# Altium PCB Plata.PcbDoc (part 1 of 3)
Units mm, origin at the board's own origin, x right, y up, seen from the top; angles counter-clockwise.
Board outline 225.2 x 126.25 mm, 5 copper layers (Top Layer, Mid-Layer 1, Mid-Layer 2, Mid-Layer 3, Bottom Layer); 204 components, 178 nets, 840 pads, 262 vias.
Unrouted connection lines stored in the file: 7.
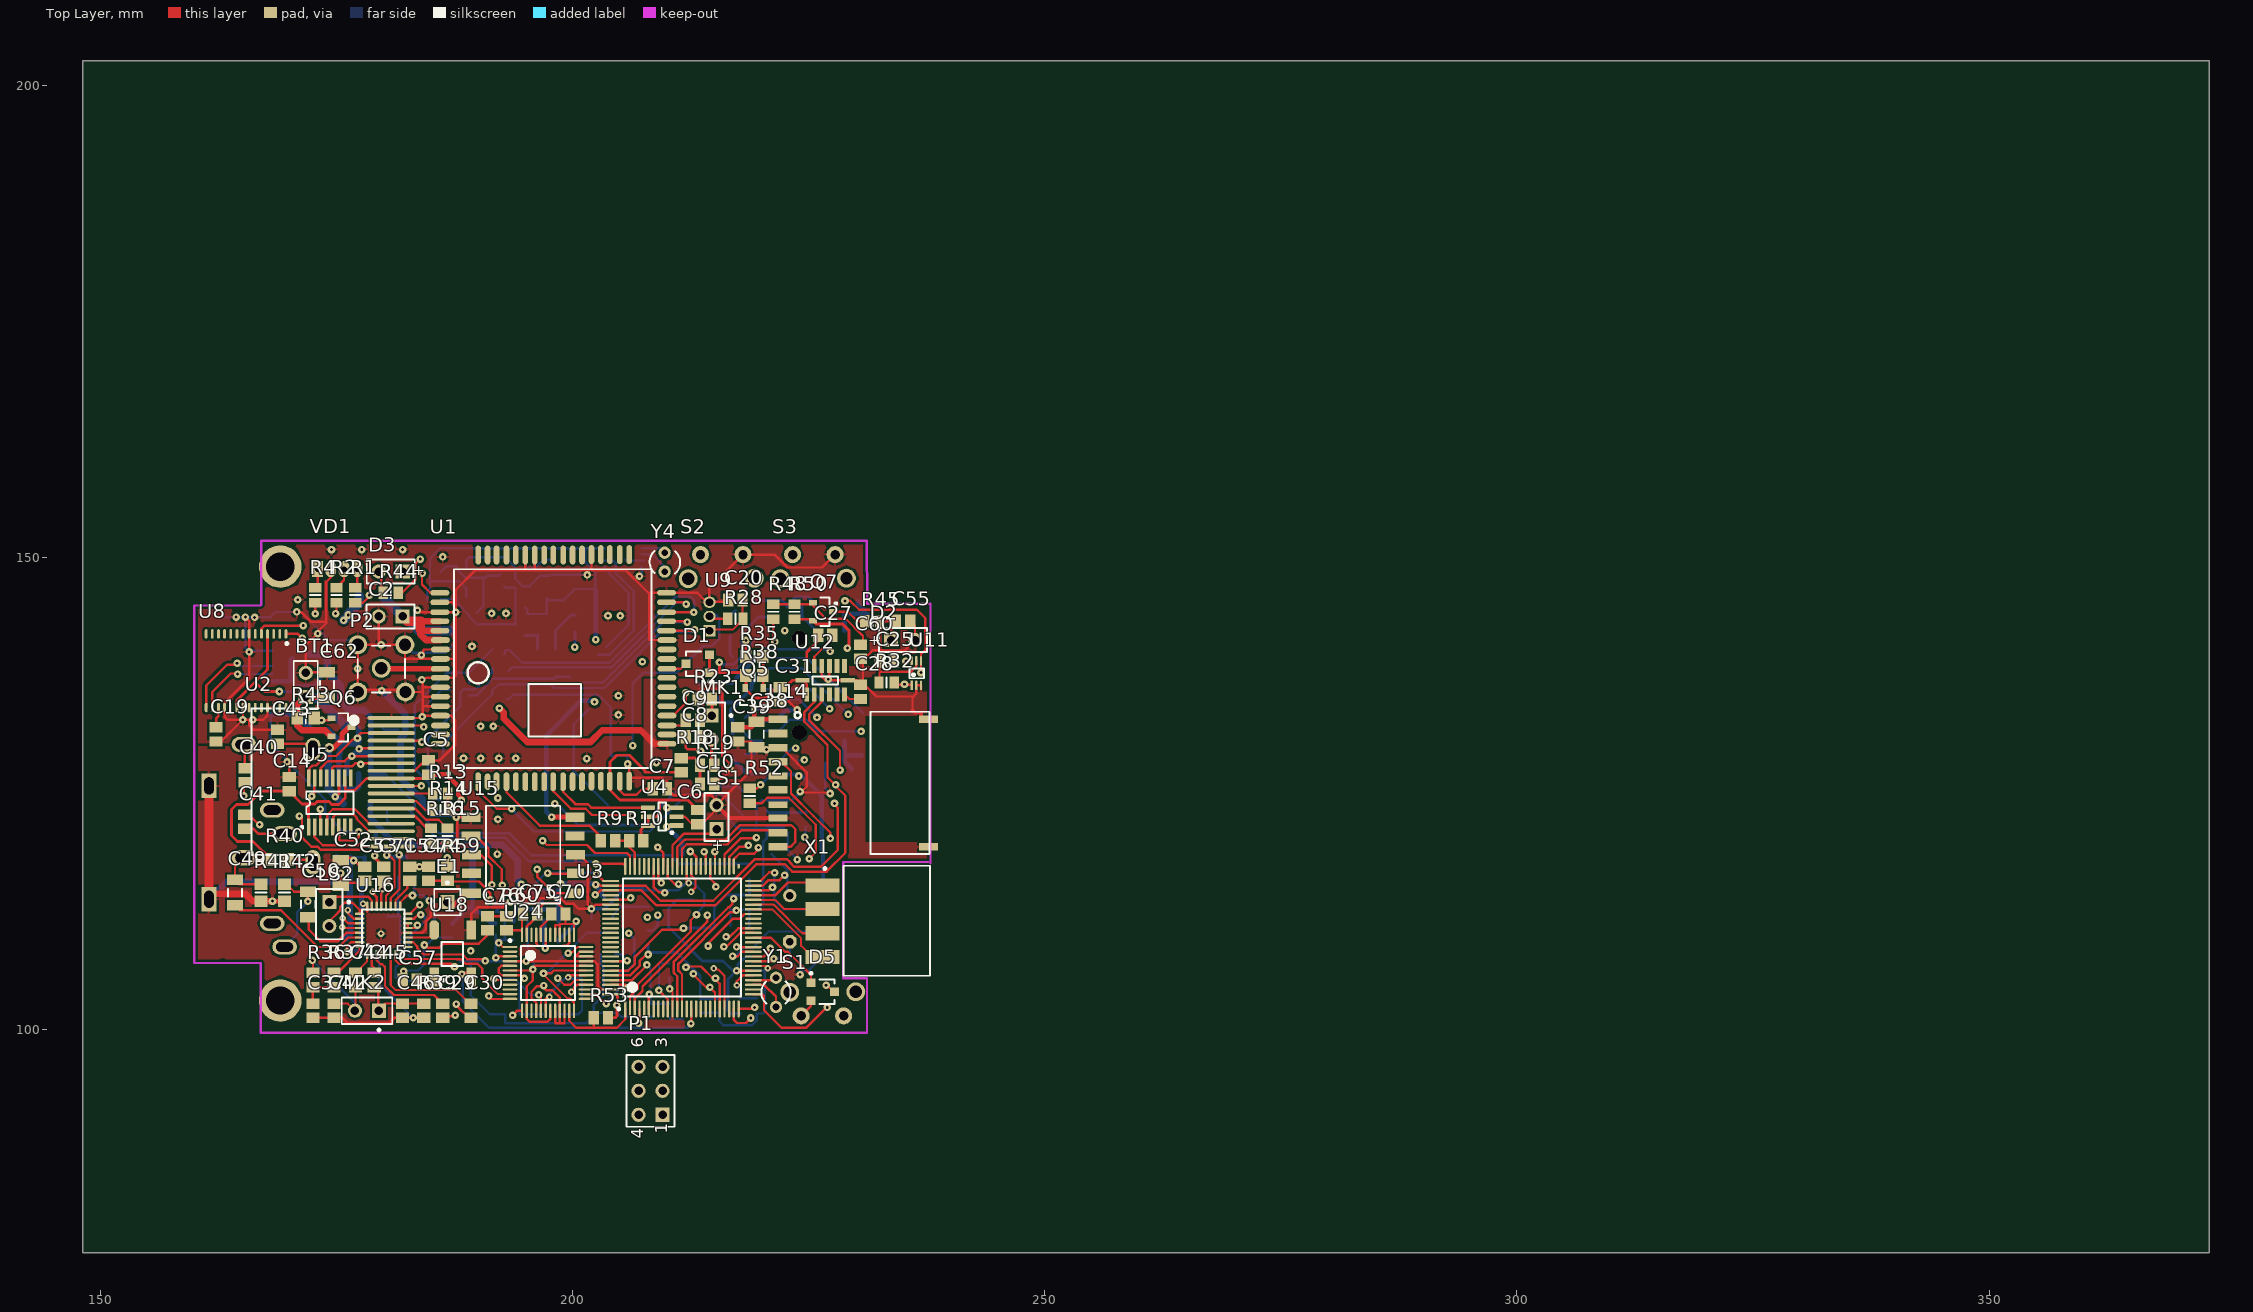
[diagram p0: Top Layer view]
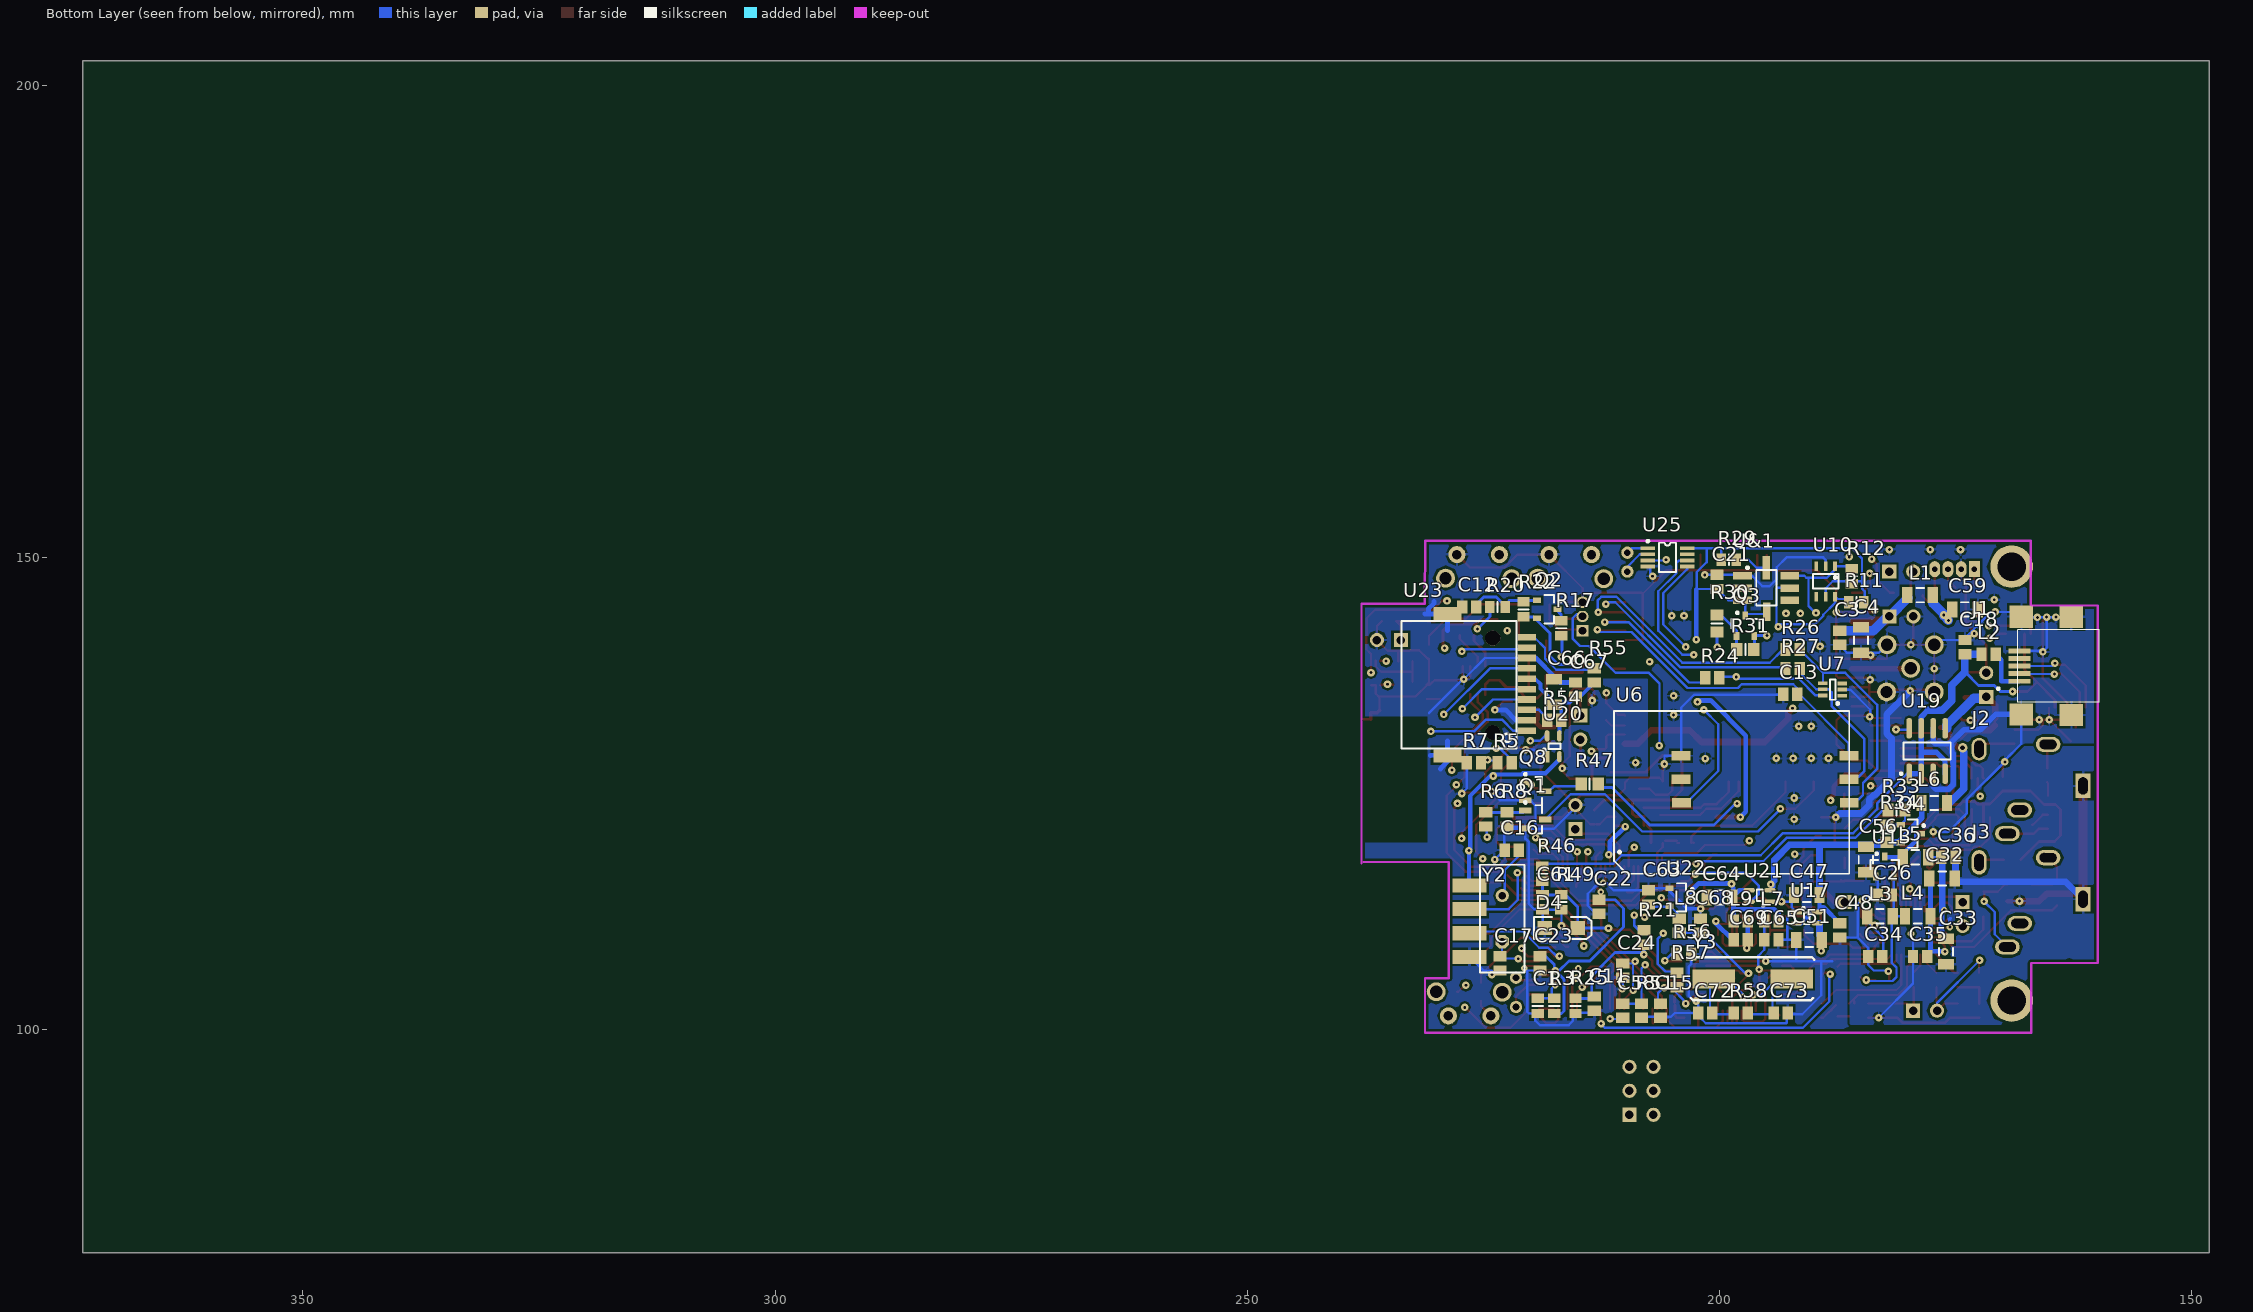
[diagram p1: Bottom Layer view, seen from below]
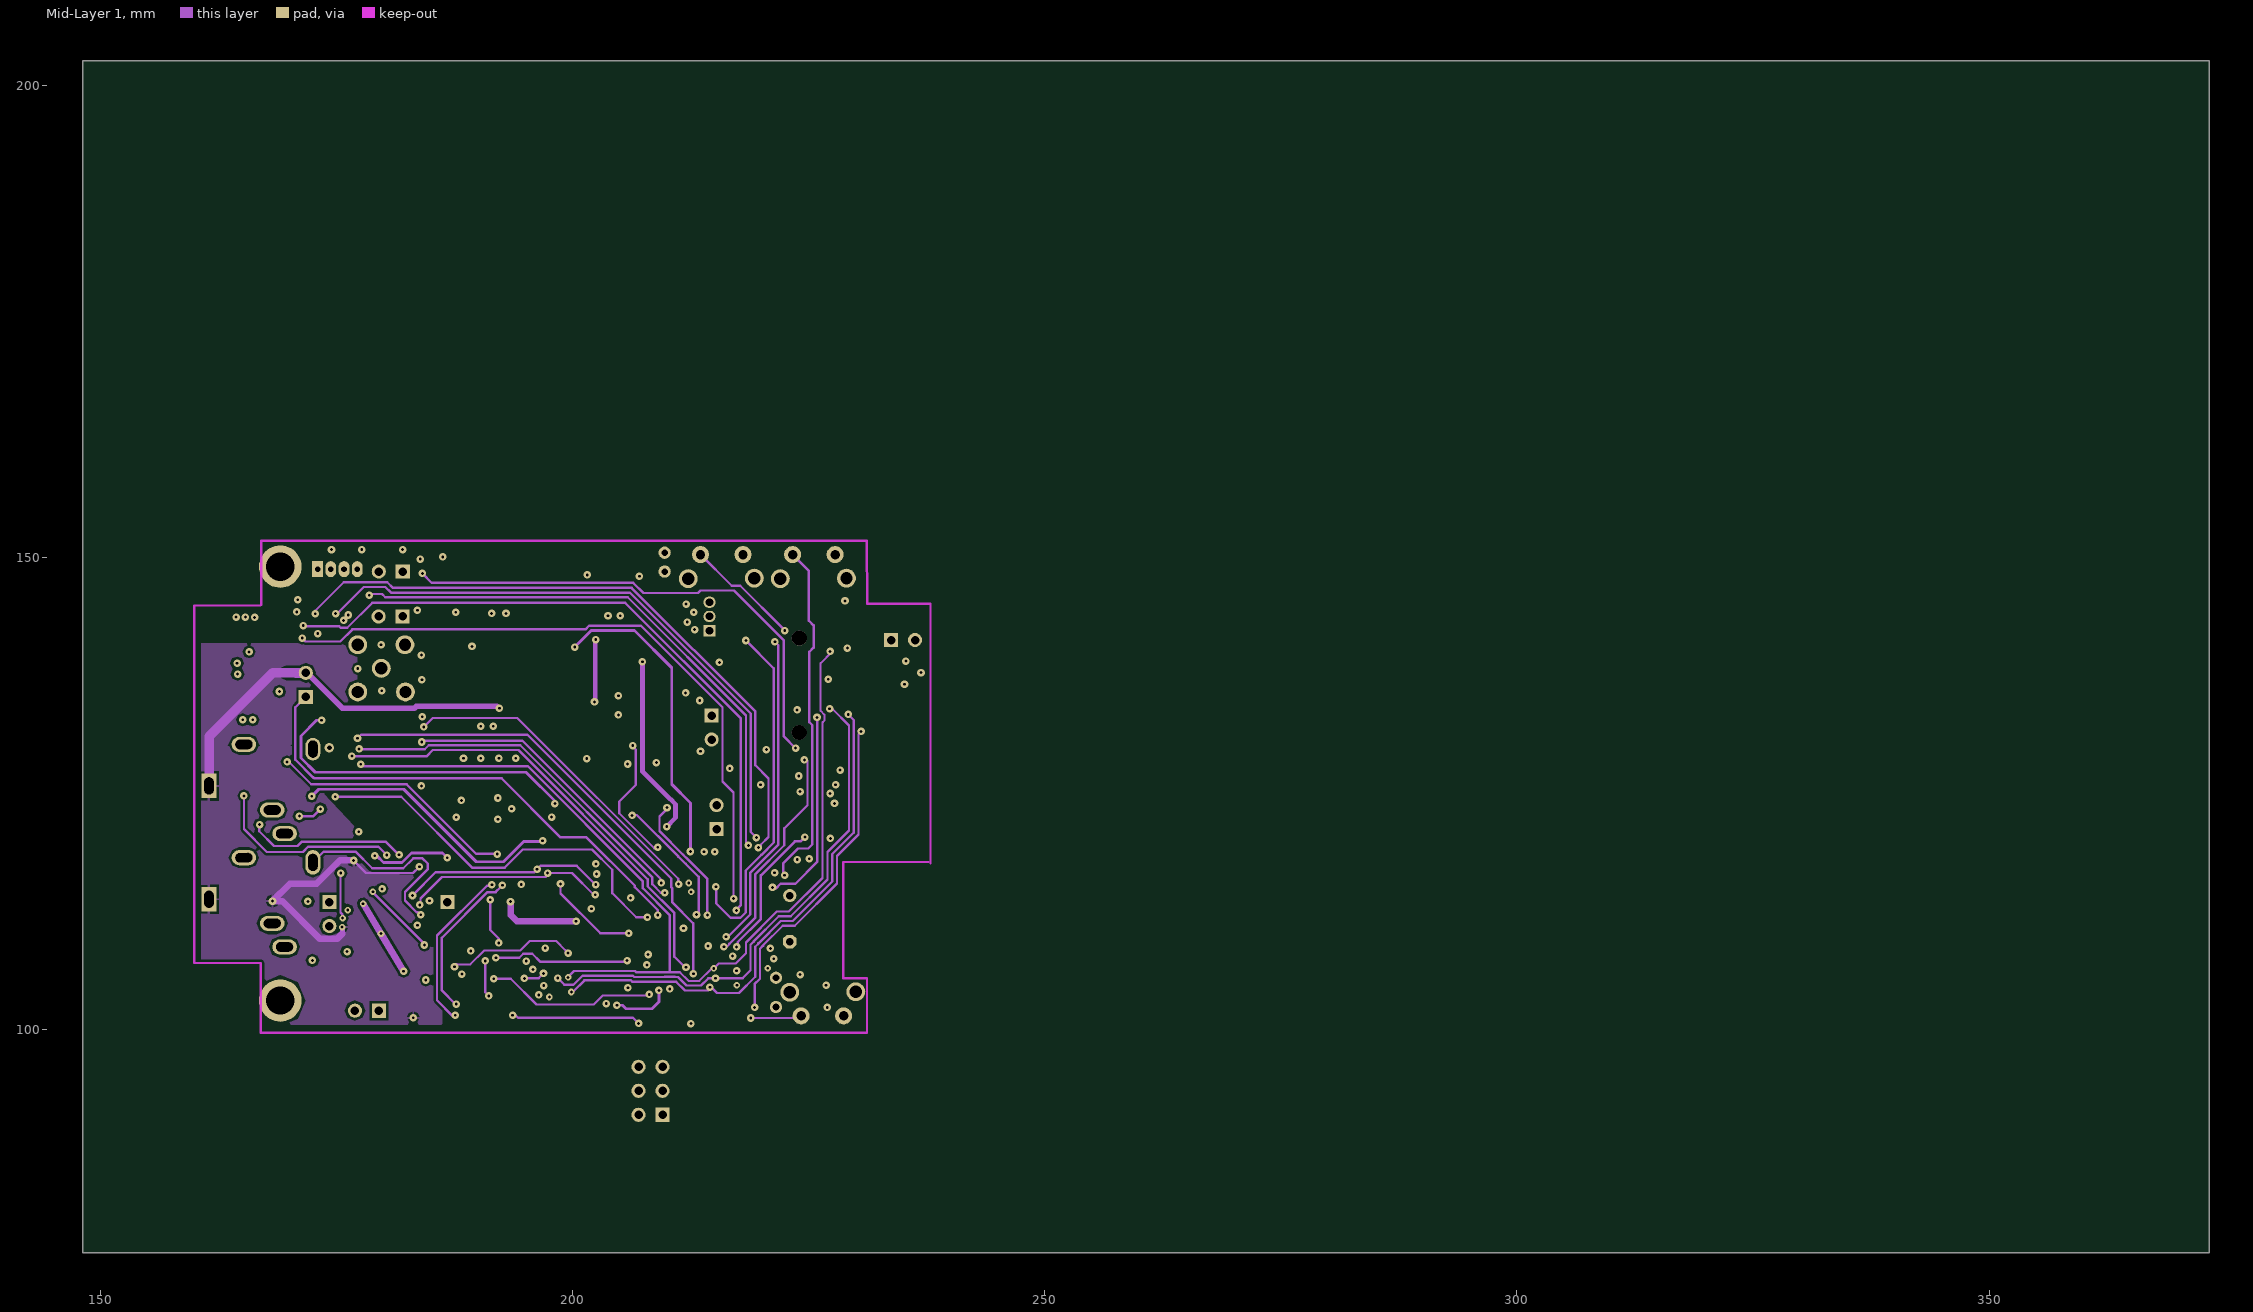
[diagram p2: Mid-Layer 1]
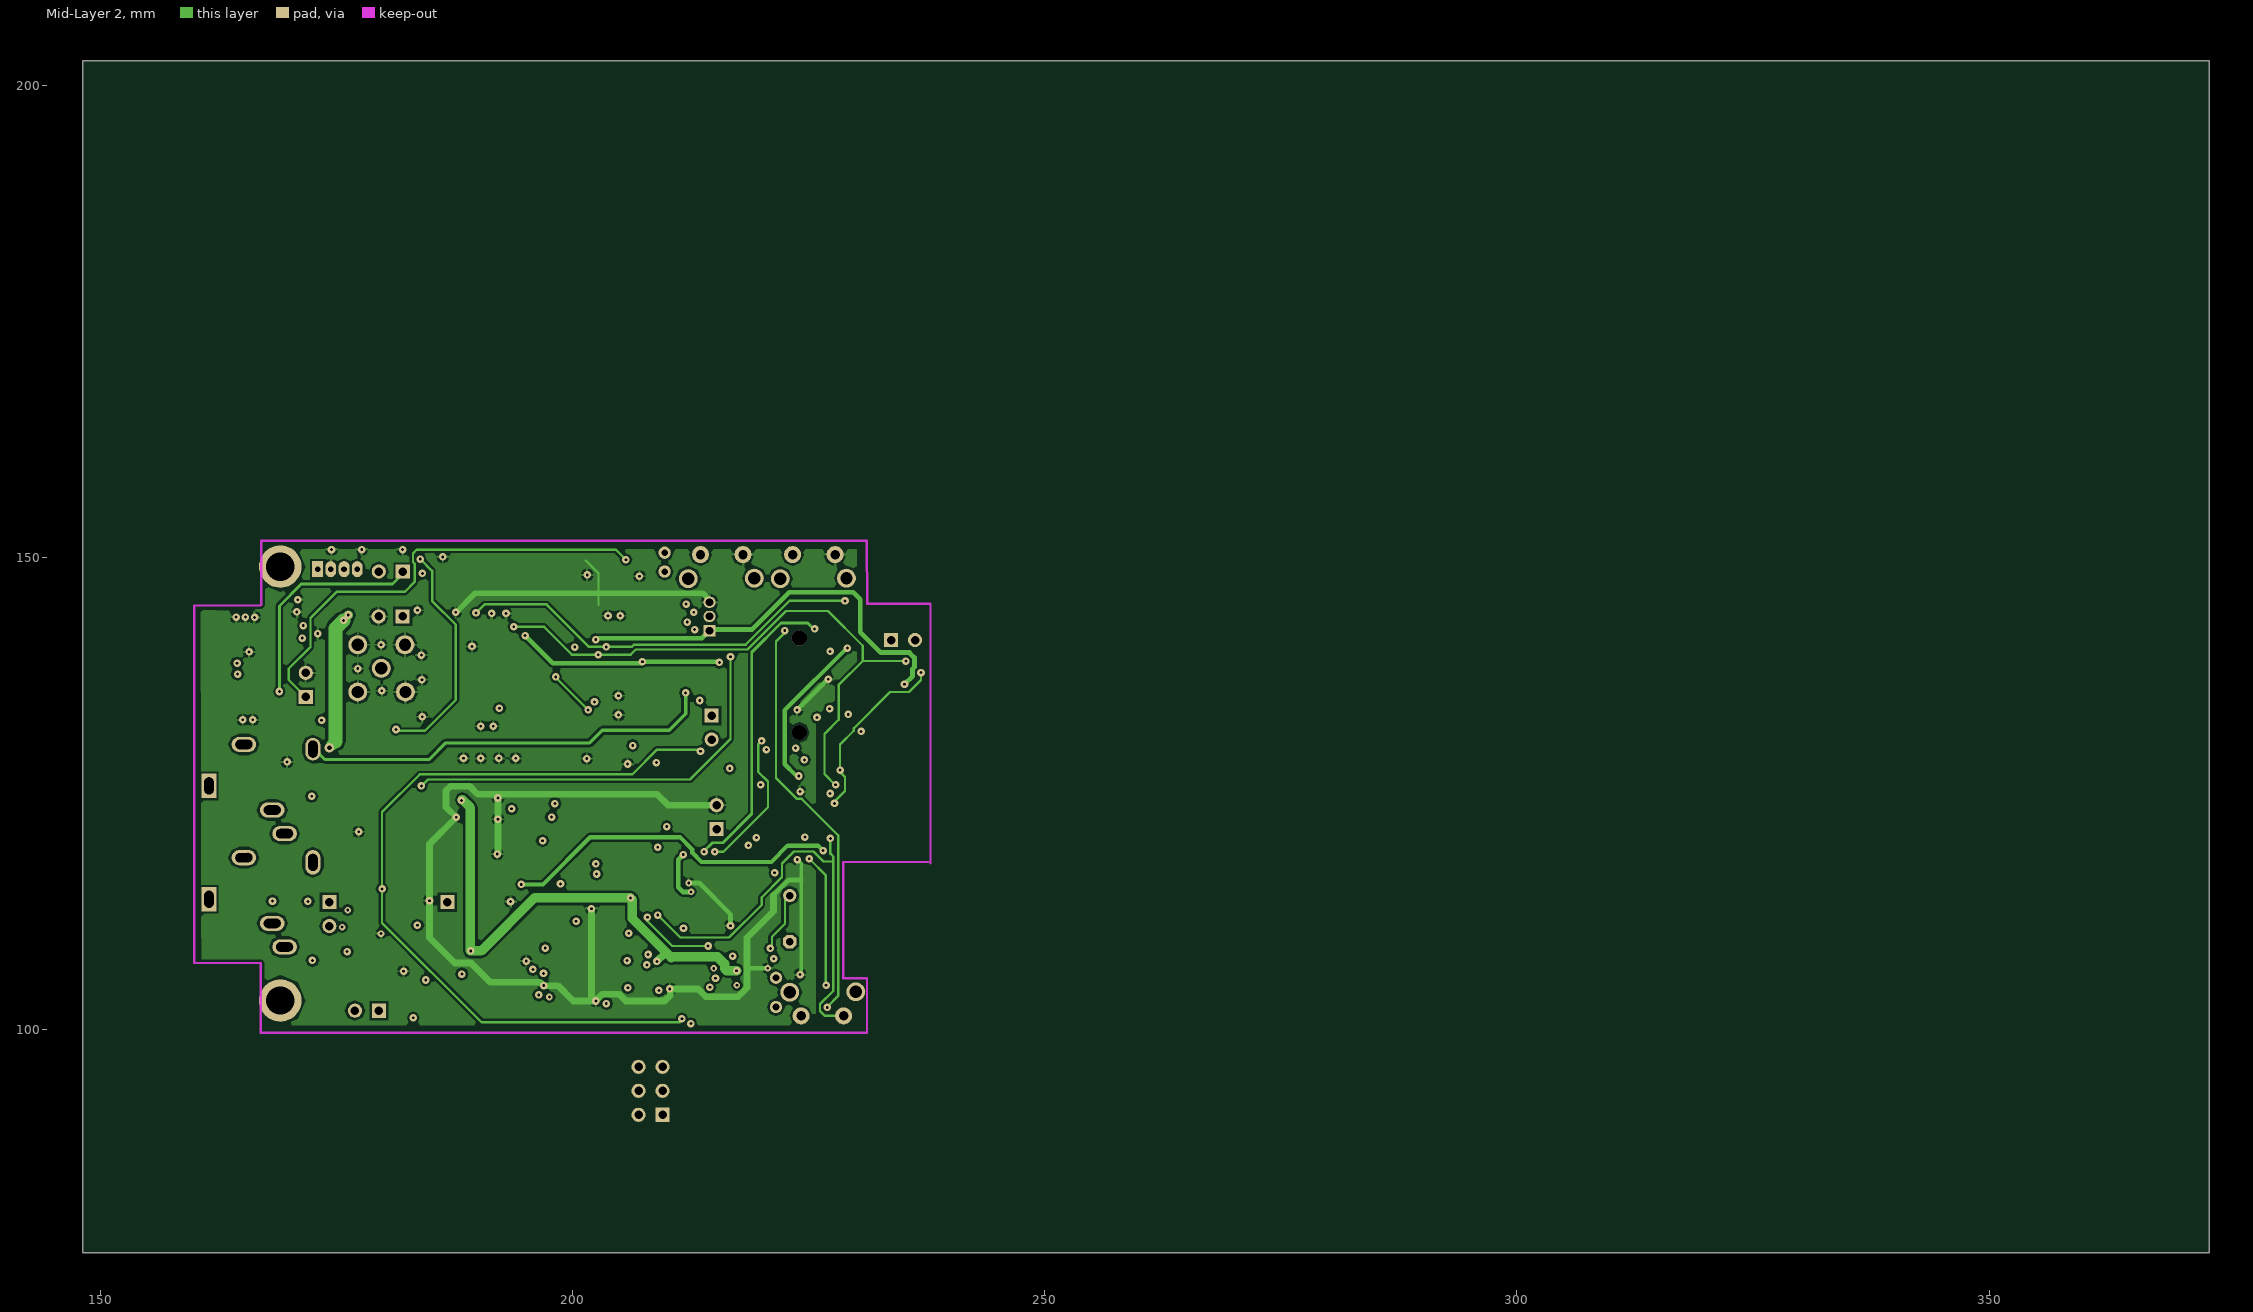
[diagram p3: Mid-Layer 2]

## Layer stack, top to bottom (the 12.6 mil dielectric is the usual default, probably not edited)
Top Layer: signal copper 0.0356
Dielectric: prepreg 0.32, FR-4, Dk 4.8
Mid-Layer 1: signal copper 0.0356
Dielectric: prepreg 0.32, FR-4, Dk 4.8
Mid-Layer 2: signal copper 0.0356
Dielectric: prepreg 0.32, FR-4, Dk 4.8
Mid-Layer 3: signal copper 0.0356
Dielectric: core 0.32, FR-4, Dk 4.8
Bottom Layer: signal copper 0.0356

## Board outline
148.125,202.6 373.325,202.6 373.325,76.35 148.125,76.35

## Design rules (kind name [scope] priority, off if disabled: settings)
AcuteAngle [All] p1: minimum=6.00000000000000E+0001
Clearance [All] p1: gap=0.25
Length Length_3 [All] p1: maxlimit=2540 minlimit=0
Length STEP4 [InNet('STEP4')] p2: maxlimit=254 minlimit=0
Length STEP3 [InNet('STEP3')] p3: maxlimit=254 minlimit=0
Length STEP2 [InNet('STEP2')] p4: maxlimit=254 minlimit=0
Length STEP1 [InNet('STEP1')] p5: maxlimit=254 minlimit=0
Length 1 [InNet('CLK')] p6: maxlimit=254 minlimit=0
MaximumViaCount [All] p1: limit=100
MinimumAnnularRing [All] p1: minimumring=0.25
PolygonConnect [All] p1: connectstyle=Relief reliefconductorwidth=0.254 reliefentries=4 polygonreliefangle="90 Angle"
RoomDefinition "Центральный процессор" [InComponentClass('Центральный процессор')] p1: confinementstyle=ConfineIn formatcopy=TRUE lockcomponents=FALSE outline 374.471,76.557 390.472,76.557 390.472,82.308 374.471,82.308
RoutingLayers [All] p1: top layer_v5=TRUE mid layer 1_v5=FALSE mid layer 2_v5=FALSE mid layer 3_v5=FALSE bottom layer_v5=TRUE
RoutingVias [All] p1: holewidth=0.3 width=0.8 viastyle="Through Hole" minholewidth=0.3 minwidth=0.8 maxholewidth=0.3 maxwidth=0.8
SMDToPlane [All] p1: distance=393701
SilkscreenOverComponentPads [All] p1: minsilkscreentomaskgap=0.254
SolderMaskExpansion [All] p1: expansion=0.102
Width VCC3 [InNet('VCC3')] p1: maxlimit=1 minlimit=0.25 preferedwidth=0.25
Width VCC5 [InNet('VCC5')] p2: maxlimit=1 minlimit=0.25 preferedwidth=0.25
Width GND [InNet('GND')] p3: maxlimit=1.4 minlimit=0.25 preferedwidth=0.25
Width [All] p4: maxlimit=0.55 minlimit=0.24 preferedwidth=0.25
26 further rules are at their usual default settings.

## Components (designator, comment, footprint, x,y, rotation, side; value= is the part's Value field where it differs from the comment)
BT1 "Battery" BAT-2 171.75,136.5 r90 top
C1 "Cap Semi" 6-0805_L 219.25,102.5 r90 bottom
C2 "Cap Pol2" HDR1X2 182,143.75 r180 top
C3 "Cap Semi" C0805 187.25,141.5 r270 bottom
C4 "Cap Semi" C1206 185,141.25 r270 bottom
C5 "Cap Semi" C0805 184.75,127.75 r90 top
C6 "Cap Semi" C0805 213.25,122.5 r90 top
C7 "Cap Semi" C0805 209.25,125.5 r180 top
C8 "Cap Semi" C0805 212.75,131 r180 top
C9 "Cap Semi" C0805 212.75,132.75 r180 top
C10 "Cap Semi" C0805 214.25,126 r180 top
C11 "Cap Semi" C0805 213.25,102.75 r90 bottom
C12 "Cap Semi" C0805 226.5,144.75 r0 bottom
C13 "Cap Semi" C0805 192.5,135.5 r180 bottom
C14 "Cap Semi" C0805 170,126 r90 top
C15 "Cap Semi" C0805 206.25,102 r90 bottom
C16 "Cap Semi" C0805 222,119 r0 bottom
C17 "Cap Semi" C0805 223.25,107 r270 bottom
C18 "Cap Semi" C0805 174,140.5 r270 bottom
C19 "Cap Semi" C0805 162.25,131.25 r90 top
C20 "Cap Semi" C0805 217.25,145.5 r180 top
C21 "Cap Semi" C0805 200.25,147.4 r270 bottom
C22 "Cap Semi" C0805 212.75,113 r90 bottom
C23 "Cap Semi" C0805 219,107 r90 bottom
C24 "Cap Semi" C0805 210.25,106.25 r90 bottom
C25 "Cap Semi" C0805 233.25,139 r0 top
C26 "Cap Semi" C0805 182.5,114.25 r180 bottom
C27 "Cap Semi" C0805 226.75,141.75 r0 top
C28 "Cap Semi" C0805 230.5,135.75 r270 top
C29 "Cap Semi" C0805 186.25,102 r90 top
C30 "Cap Semi" C0805 189.25,102 r90 top
C31 "Cap Semi" C0805 222,135.5 r270 top
C32 "Cap Pol2" C1206 176.425,116 r180 bottom
C33 "Cap Pol2" C1206 176,108.25 r270 bottom
C34 "Cap Semi" C0805 183.5,107.75 r0 bottom
C35 "Cap Semi" C0805 178.75,107.75 r0 bottom
C36 "Cap Semi" C0805 175.75,118.25 r180 bottom
C37 "Cap Semi" C0805 172.5,102 r270 top
C38 "Cap Pol2" C1206 219.5,131.25 r270 top
C39 "Cap Semi" C0805 217.5,131.25 r270 top
C40 "Cap Semi" C0805 165.299,126.937 r90 top
C41 "Cap Semi" C0805 165.25,122 r270 top
C42 "Cap Semi" C0805 174.75,102 r90 top
C43 "Cap Semi" C0805 168.75,131 r270 top
C44 "Cap Semi" C0805 177,105.25 r90 top
C45 "Cap Semi" C0805 179,105.25 r90 top
C46 "Cap Semi" C0805 182,102 r90 top
C47 "Cap Semi" C1206 190.75,114.25 r180 bottom
C48 "Cap Semi" C0805 187.25,110.5 r270 bottom
C49 "Cap Semi" C1206 164.25,114.5 r90 top
C50 "Cap Semi" C1206 172,113.25 r90 top
C51 "Cap Semi" C1206 190.5,109.5 r180 bottom
C52 "Cap Pol2" C1206 175.45,116.575 r90 top
C53 "Cap Semi" C0805 178,116.5 r90 top
C54 "Cap Semi" C0805 182.75,116.5 r90 top
C55 "Cap Semi" C0805 235,143.25 r180 top
C56 "Cap Semi" C1206 184.5,118 r270 bottom
C57 "Cap Semi" C0805 182.75,105.25 r180 top
C58 "Cap Semi" C0805 210.25,102 r90 bottom
C59 "Cap Semi" C1206 174,144.5 r180 bottom
C60 "Cap Semi" C0805 230.5,140 r90 top
C61 "Cap Semi" C0805 218.75,113.5 r270 bottom
C62 "Cap Semi" C1206 174,136.5 r90 top
C63 "Cap Pol2" C0805 207.5,114 r90 bottom
C64 "Cap Semi" C1206 200,114 r0 bottom
C65 "Cap Semi" C0805 194.5,109.5 r0 bottom
C66 "Cap Semi" C1206 217.5,135.75 r270 bottom
C67 "Cap Semi" C0805 215.25,136 r90 bottom
C68 "Cap Semi" C0805 202,111 r270 bottom
C69 "Cap Semi" C0805 197.75,109.5 r180 bottom
C70 "Cap Semi" C0805 198.5,112.25 r0 top
C71 "Cap Semi" C0805 180,116.5 r270 top
C72 "Cap Semi" C0805 201.5,101.75 r0 bottom
C73 "Cap Semi" C0805 193.5,101.75 r180 bottom
C74 "Cap Semi" C0805 184.75,116.5 r90 top
C75 "Cap Semi" C0805 195.5,112.25 r180 top
C76 "Cap Semi" C0805 191,111.25 r270 top
D1 "BAS70-05" SOT-23 213.25,138.75 r90 top
D2 "LED3" BAT-2 235,141.25 r0 top
D3 "LED3" BAT-2 180.75,148.5 r180 top
D4 "BZV55-C3V3" 3.2X1.6X1.1 216.75,110.75 r180 bottom
D5 "BAS70-05" SOT-23 226.5,104 r270 top
E1 "Antenna" PIN1 186.75,113.5 r0 top
J1 "0481900001" ATB3225 164.75,138.5 r0 bottom
J2 "Phonejack Stereo SW" "AUDIO 3.5"#1 172.5,119.75 r180 bottom
J3 "Phonejack Stereo SW" "AUDIO 3.5"#2 172.5,107.75 r180 bottom
L1 "Inductor" C1206 178.75,146 r0 bottom
L2 "Inductor" C0805 171.5,139.75 r0 bottom
L3 "Inductor" C1206 183,112 r0 bottom
L4 "Inductor" C1206 179,112 r180 bottom
L5 "Inductor" C1206 179.25,118.25 r180 bottom
L6 "Inductor" C1206 177.25,124 r0 bottom
L7 "Inductor" C0805 194.5,111.5 r180 bottom
L8 "Inductor" C0805 204.25,111 r90 bottom
L9 "Inductor" C0805 197.75,111.5 r0 bottom
LS1 "Buzzer" BAT-2 215.25,122.5 r90 top
LS2 "Speaker" PIN2 174.25,113.5 r270 top
MK1 "Mic2" PIN2 214.725,133.25 r270 top
MK2 "Mic2" PIN2 179.5,102 r180 top
P1 "Header 3X2A" HDR2X3_CEN 209.525,90.975 r90 top
P2 "COAX-M" sma 179.75,138.25 r0 top
Q1 "MMBTA42   BC817-25" SOT23_N 219.5,122.25 r180 bottom
Q2 "IRLML9301" VT 218.25,144.5 r270 bottom
Q3 "IRLML9301" VT 197.25,142.75 r180 bottom
Q4 "IRLML9301" VT 179.75,120.75 r270 bottom
Q5 "IRLML9301" VT 219.25,135.1 r180 top
Q6 "IRLML9301" VT 175.5,132 r270 top
Q7 "IRLML9301" VT 226.5,144.25 r270 top
Q8 "BC847 BC817" SOT23_N 219.5,125.25 r180 bottom
R1 "Res2" 6-0805_L 177,146 r90 top
R2 "Res2" 6-0805_L 175,146 r90 top
R3 "Res2" 6-0805_L 217.5,102.5 r270 bottom
R4 "Res2" 6-0805_L 172.75,146 r90 top
R5 "Res2" C0805 222.75,128.25 r0 bottom
R6 "Res2" C0805 224.75,122.25 r90 bottom
R7 "Res2" C0805 226,128.25 r0 bottom
R8 "Res2" C0805 222.5,122.25 r270 bottom
R9 "Res2" C0805 203.75,120 r0 top
R10 "Res2" C0805 206.75,120 r0 top
R11 "Res2" 6-0805_L 185.5,145.25 r180 bottom
R12 "Res2" 6-0805_L 186,148 r270 bottom
R13 "Res2" 6-0805_L 186,125 r180 top
R14 "Res2" 6-0805_L 186,123.25 r180 top
R15 "Res2" 6-0805_L 186.75,120.5 r90 top
R16 "Res2" 6-0805_L 185,120.5 r90 top
R17 "Res2" 6-0805_L 216.75,142.5 r90 bottom
R18 "Res2" C0805 211.5,128 r270 top
R19 "Res2" C0805 214.25,128 r180 top
R20 "Res2" 6-0805_L 223.5,144.75 r180 bottom
R21 "Res2" C0805 208,109.75 r270 bottom
R22 "Res2" 6-0805_L 220.75,144.5 r270 bottom
R23 "Res2" C0805 214,135 r0 top
R24 "Res2" C0805 200.75,137.25 r0 bottom
R25 "Res2" 6-0805_L 215.25,102.5 r270 bottom
R26 "Res2" C0805 192.25,140.25 r0 bottom
R27 "Res2" C0805 192.25,138.25 r0 bottom
R28 "Res2" 6-0805_L 217.25,143.5 r180 top
R29 "Res2" 6-0805_L 199,149.75 r0 bottom
R30 "Res2" 6-0805_N 200.25,143 r270 bottom
R31 "Res2" 6-0805_N 197.25,140.25 r0 bottom
R32 "Res2" 6-0805_L 233.25,136.75 r0 top
R33 "Res2" 6-0805_N 181.25,123.25 r0 bottom
R34 "Res2" 6-0805_N 182.25,120.75 r90 bottom
R35 "Res2" 6-0805_N 219.25,139.5 r180 top
R36 "Res2" C0805 172.5,105.25 r270 top
R37 "Res2" C0805 174.75,105.25 r270 top
R38 "Res2" 6-0805_N 219.25,137.5 r0 top
R39 "Res2" C0805 184.25,102 r90 top
R40 "Res2" 6-0805_N 169,118 r0 top
R41 "Res2" 6-0805_N 167,114.5 r270 top
R42 "Res2" 6-0805_N 169.5,114.5 r270 top
R43 "Res2" 6-0805_N 171.75,133 r0 top
R44 "Res2" 6-0805_L 180.75,146.25 r0 top
R45 "Res2" 6-0805_L 231.75,143.25 r0 top
R46 "Res2" 6-0805_L 218.75,116.5 r90 bottom
R47 "Res2" 6-0805_N 213.75,126 r0 bottom
R48 "Res2" 6-0805_L 221.25,144.25 r90 top
R49 "Res2" 6-0805_L 216.75,113.5 r90 bottom
R50 "Res2" 6-0805_L 223.5,144.25 r90 top
R51 "Res2" C0805 208.25,102 r270 bottom
R52 "Res2" 6-0805_L 218.75,124.75 r270 top
R53 "Res2" C0805 203,101.25 r180 top
R54 "Res2" C0805 217.5,132.75 r0 bottom
R55 "Res2" C0805 213.25,137.5 r90 bottom
R56 "Res2" C0805 203.75,108 r0 bottom
R57 "Res2" C0805 204.5,105.25 r270 bottom
R58 "Res2" C0805 197.75,101.75 r180 bottom
R59 "Res2" C0805 186.75,116.5 r270 top
R60 "Res2" C0805 193,111.25 r270 top
S1 "Key" Key 223,94 r0 top
S2 "Key" Key 219.25,157.75 r180 top
S3 "Key" Key 229,157.75 r180 top
U1 "SIM900" SIM900_ 186,126.25 r90 top
U2 "2_8LCD" "LCD 2.8" 192,129 r0 top
U3 "ATmega2560V-8AU" 100 211.5,109.75 r0 top
U4 "ПУ" "Преобразователь уровней SN74LVC1T45" 208,123.5 r180 top
U5 "XPT2046    ADS7846E/2K5" TC 174.25,124 r0 top
U6 "Sim card" SIM-06 186.25,116.5 r0 bottom
U7 "SMF05CT1G" SMF05CT1G 188,136 r0 bottom
U8 "FT232RL" FT232RL 165.25,138 r270 top
U9 "DS18B20" DS18B20 214.5,142.25 r90 top
U10 "SHT21" Датчик 188.75,147.5 r270 bottom
U11 "BH1750" BH1750 236.5,137.75 r90 top
U12 "lsm303dlhc" lsm303dlhc 226.75,137 r90 top
U13 "MCP1700T-3002E/TT" VT 182.5,117.25 r180 bottom
U14 "Gms-g6a" "GPS Gms-g6a" 229.75,126 r0 top
U15 "Tea5767 module" "FM AR1310" 194.75,118.5 r180 top
U16 "ALC5621" "AUDIO CODEC" 182.5,113 r90 top
U17 "ncp698sq30t1g" St_3V0 190.75,111.75 r180 bottom
U18 "KXO-V97" 25 187.25,108 r90 top
U19 "Max1811" SOIC8N_N 178,129.5 r90 bottom
U20 "ncp698sq30t1g" St_3V0_ver2 217.25,130.25 r90 bottom
U21 "ncp698sq30t1g" St_3V0 195.75,114.25 r0 bottom
U22 "MCP1700T-1802E/TT" VT 204.25,114 r270 bottom
U23 "microSD" microSD_PCB 221.5,133.25 r0 bottom
U24 "VS1053" DIP8 197.5,106 r0 top
U25 "DS1339U-3" 8uSOP 205.5,150 r270 bottom
U&1 "Bmp085" "Датчик давления Bmp085" 194.5,146.25 r180 bottom
VD1 "VD?" RGB_5mm_Led 173,148.75 r0 top
X1 "Xmain" Xmain 233.25,111.5 r180 top
Y1 "XTAL 32 кГц" R38 221.538,103.937 r0 top
Y2 "8 MHz" HC-49U 223,111.75 r90 bottom
Y3 "XTAL 12.288" ZQ 193,105.375 r180 bottom
Y4 "XTAL" 32768 209.75,149.5 r0 top

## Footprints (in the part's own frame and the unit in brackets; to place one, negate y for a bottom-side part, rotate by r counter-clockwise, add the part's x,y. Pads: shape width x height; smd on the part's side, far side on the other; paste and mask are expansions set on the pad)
3.2X1.6X1.1 [mm] "SMT LED; 2 Flat Leads"
  rect 1.5x1.5 smd: 1(-1.75,0) 2(1.75,0)
  silkscreen extent -2.9,-1.15 3.2,1.15
6-0805_L [mm] "Chip Resistor, Body 2.0x1.2mm, IPC High Density"
  rect 1x1.3 smd: 1(-0.8,0) 2(0.8,0)
  silkscreen extent 0,-0.55 0,0.55, body extent -1.07,-0.7 1.07,0.7, height 0.7
6-0805_N [mm] "Chip Resistor, Body 2.0x1.2mm, IPC Medium Density"
  rect 1.2x1.4 smd: 1(-0.9,0) 2(0.9,0)
  silkscreen extent 0,-0.6 0,0.6, body extent -1.07,-0.7 1.07,0.7, height 0.7
8uSOP [mm] "Shrink Small Outline; 8 Leads; Body Width 3 mm; Pitch 0.65 mm"
  rect 0.4x1.55 smd: 1(-0.975,-2.075) 2(-0.325,-2.075) 3(0.325,-2.075) 4(0.975,-2.075) 5(0.975,2.075) 6(0.325,2.075) 7(-0.325,2.075) 8(-0.975,2.075)
  silkscreen extent -1.85,-2.2 1.55,0.9
25 [mm]
  rect 2x1 smd: 1(-2.413,-2.032) 2(2.54,-2.032) 4(-2.413,1.905)
  oct 2x1 smd: 3(2.54,1.905)
  silkscreen extent -2.92,-1.14 1.27,1.14
100 [mm] "20-Pin Small Outline Integrated Circuit 1.27 mm Pitch, IPC Low Density"
  oval 0.25x1.8 smd: 1(-5.914,-7.564) 2(-5.414,-7.564) 3(-4.914,-7.564) 4(-4.414,-7.564) 5(-3.914,-7.564) 6(-3.414,-7.564) 7(-2.914,-7.564) 8(-2.414,-7.564) 9(-1.914,-7.564) 10(-1.414,-7.564) 11(-0.914,-7.564) 12(-0.414,-7.564) 13(0.086,-7.564) 14(0.586,-7.564) 15(1.086,-7.564) 16(1.586,-7.564) 17(2.086,-7.564) 18(2.586,-7.564) 19(3.086,-7.564) 20(3.586,-7.564) 21(4.086,-7.564) 22(4.586,-7.564) 23(5.086,-7.564) 24(5.586,-7.564) 25(6.086,-7.564) 53(5.086,7.536) 54(4.586,7.536) 55(4.086,7.536) 56(3.586,7.536) 57(3.086,7.536) 58(2.586,7.536) 59(2.086,7.536) 60(1.586,7.536) 61(1.086,7.536) 62(0.586,7.536) 63(0.086,7.536) 64(-0.414,7.536) 65(-0.914,7.536) 66(-1.414,7.536) 67(-1.914,7.536) 68(-2.414,7.536) 69(-2.914,7.536) 70(-3.414,7.536) 71(-3.914,7.536) 72(-4.414,7.536) 73(-4.914,7.536) 74(-5.414,7.536) 75(-5.914,7.536)
  oval 1.8x0.25 smd: 26(7.636,-6.014) 27(7.636,-5.514) 28(7.636,-5.014) 29(7.636,-4.514) 30(7.636,-4.014) 31(7.636,-3.514) 32(7.636,-3.014) 33(7.636,-2.514) 34(7.636,-2.014) 35(7.636,-1.514) 36(7.636,-1.014) 37(7.636,-0.514) 38(7.636,-0.014) 39(7.636,0.486) 40(7.636,0.986) 41(7.636,1.486) 43(7.636,2.486) 44(7.636,2.986) 45(7.636,3.486) 46(7.636,3.986) 47(7.636,4.486) 48(7.636,4.986) 49(7.636,5.486) 76(-7.464,5.986) 77(-7.464,5.486) 78(-7.464,4.986) 79(-7.464,4.486) 80(-7.464,3.986) 81(-7.464,3.486) 82(-7.464,2.986) 83(-7.464,2.486) 84(-7.464,1.986) 85(-7.464,1.486) 86(-7.464,0.986) 87(-7.464,0.486) 88(-7.464,-0.014) 89(-7.464,-0.514) 90(-7.464,-1.014) 91(-7.464,-1.514) 92(-7.464,-2.014) 93(-7.464,-2.514) 94(-7.464,-3.014) 95(-7.464,-3.514) 96(-7.464,-4.014) 97(-7.464,-4.514) 98(-7.464,-5.014) 99(-7.464,-5.514) 100(-7.464,-6.014)
  oval 1.7x0.25 smd: 42(7.636,1.986) 50(7.636,5.986)
  oval 0.25x0.5 smd: 51(6.086,7.536)
  oval 0.25x1.7 smd: 52(5.586,7.536)
  silkscreen extent -6.74,-7.69 6.34,6.24, body extent -6.91,-7.01 7.09,6.99, height 1.2
32768 [mm] "4148m"
  round 1.3 hole 0.7: 1(0,-1) 2(0,1)
  silkscreen extent -1.59,-1.19 1.64,1.2
ATB3225 [mm] "ATB3225"
  rect 2.35x0.5 smd: 1(3.462,1.6) 2(3.463,0.8) 3(3.463,0) 4(3.463,-0.8) 5(3.463,-1.6)
  rect 2.5x2.35 smd: MH1(3.288,5.125) MH2(-2.013,5.175) MH3(-2.013,-5.175) MH4(3.288,-5.225)
  silkscreen extent -4.96,-3.85 5.84,3.85
"AUDIO 3.5"#1 [mm] "20-Pin Small Outline Integrated Circuit 1.27 mm Pitch, IPC Low Density"
  rect 1.6x2.6 hole 1 slot 1.8 at 89.3 deg: 1(11,6.05)
  oval 2.6x1.6 hole 1 slot 1.8 at 179.3 deg: 2(7.3,10.45) 3(4.3,3.5) 4(3,1)
  oval 1.6x2.4 hole 1 slot 1.8 at 89.3 deg: 5(0,9.95)
"AUDIO 3.5"#2 [mm] "20-Pin Small Outline Integrated Circuit 1.27 mm Pitch, IPC Low Density"
  rect 1.6x2.6 hole 1 slot 1.8 at 89.3 deg: 1(11,6.05)
  oval 2.6x1.6 hole 1 slot 1.8 at 179.3 deg: 2(7.3,10.45) 3(4.3,3.5) 4(3,1)
  oval 1.6x2.6 hole 1 slot 1.8 at 89.3 deg: 5(0,9.95)
"AUDIO CODEC" [mm] "20-Pin Small Outline Integrated Circuit 1.27 mm Pitch, IPC Low Density"
  oval 1x0.25 smd: 1(-5.05,4.25) 2(-5.05,3.75) 3(-5.05,3.25) 4(-5.05,2.75) 5(-5.05,2.25) 6(-5.05,1.75) 7(-5.05,1.25) 8(-5.05,0.75) 17(0.05,0.75) 18(0.05,1.25) 19(0.05,1.75) 20(0.05,2.25) 21(0.05,2.75) 22(0.05,3.25) 23(0.05,3.75) 24(0.05,4.25)
  oval 0.25x1 smd: 9(-4.25,-0.05) 10(-3.75,-0.05) 11(-3.25,-0.05) 12(-2.75,-0.05) 13(-2.25,-0.05) 14(-1.75,-0.05) 15(-1.25,-0.05) 16(-0.75,-0.05) 25(-0.75,5.05) 26(-1.25,5.05) 27(-1.75,5.05) 28(-2.25,5.05) 29(-2.75,5.05) 30(-3.25,5.05) 31(-3.75,5.05) 32(-4.25,5.05)
  silkscreen extent -5.05,0.3 -0.3,4.8, body extent -5.05,0 0.05,5.05, height 2.67
BAT-2 [mm] "Battery; 2 Leads"
  rect 1.5x1.5 hole 0.9: 1(-1.27,0)
  round 1.5 hole 0.9: 2(1.27,0)
  silkscreen extent -2.54,-1.27 2.54,1.27
BH1750 [mm] "20-Pin Small Outline Integrated Circuit 1.27 mm Pitch, IPC Low Density"
  rect 1x0.25 smd: 1(-1.3,0.6)
  oval 1x0.25 smd: 2(-1.3,0.1) 3(-1.3,-0.4) 4(1.3,-0.4) 5(1.3,0.1) 6(1.3,0.6)
  silkscreen extent -0.55,-0.7 0.5,0.8
C0805 [mm] "Chip Capacitor, Body 2.0x1.3mm, IPC High Density"
  rect 1.1x1.4 smd: 1(-0.75,0) 2(0.75,0)
  body extent -1.1,-0.72 1.1,0.72, height 1.4
C1206 [mm] "Chip Capacitor, Body 3.2x1.6mm, IPC High Density"
  rect 1.1x1.7 smd: 1(-1.35,0) 2(1.35,0)
  silkscreen extent -0.4,-0.75 0.4,0.75, body extent -1.7,-0.9 1.7,0.9, height 1.3
DIP8 [mm] "DIP; 8 Leads; Row Spacing 7.62 mm; Pitch 2.54 mm"
  oval 1.55x0.25 smd: 1(-4.125,2.75) 2(-4.125,2.25) 3(-4.125,1.75) 4(-4.125,1.25) 5(-4.125,0.75) 6(-4.125,0.25) 7(-4.125,-0.25) 8(-4.125,-0.75) 9(-4.125,-1.25) 10(-4.125,-1.75) 11(-4.125,-2.25) 12(-4.125,-2.75) 25(3.925,-2.75) 26(3.925,-2.25) 27(3.925,-1.75) 28(3.925,-1.25) 29(3.925,-0.75) 30(3.925,-0.25) 31(3.925,0.25) 32(3.925,0.75) 33(3.925,1.25) 34(3.925,1.75) 35(3.925,2.25) 36(3.925,2.75)
  oval 0.25x1.55 smd: 13(-2.85,-4.025) 14(-2.35,-4.025) 15(-1.85,-4.025) 16(-1.35,-4.025) 17(-0.85,-4.025) 18(-0.35,-4.025) 19(0.15,-4.025) 20(0.65,-4.025) 21(1.15,-4.025) 22(1.65,-4.025) 23(2.15,-4.025) 24(2.65,-4.025) 37(2.65,4.025) 38(2.15,4.025) 39(1.65,4.025) 40(1.15,4.025) 41(0.65,4.025) 42(0.15,4.025) 43(-0.35,4.025) 44(-0.85,4.025) 45(-1.35,4.025) 46(-1.85,4.025) 47(-2.35,4.025) 48(-2.85,4.025)
  silkscreen extent -4.25,-2.85 2.75,3.55, body extent -3.6,-3.5 3.4,3.5, height 1.6
DS18B20 [mm] "20-Pin Small Outline Integrated Circuit 1.27 mm Pitch, IPC Low Density"
  rect 1.2x1.3 hole 0.8: 1(0,0)
  oval 1.2x1.3 hole 0.8: 2(1.5,0) 3(3,0)
"FM AR1310" [mm] "20-Pin Small Outline Integrated Circuit 1.27 mm Pitch, IPC Low Density"
  rect 1.8x1 smd: 1(-5.55,4.05) 2(-5.55,1.95)
  rect 2x1 smd: 3(-5.55,0) 4(-5.5,-2) 5(-5.5,-4) 6(5.5,-4) 7(5.5,-2) 8(5.45,0) 9(5.45,1.95) 10(5.45,4.05)
  silkscreen extent -3.95,-5.2 3.9,5.15, body extent -5.55,-5.5 5.45,5.55, height 2.67
FT232RL [mm] "20-Pin Small Outline Integrated Circuit 1.27 mm Pitch, IPC Low Density"
  oval 1x0.3 smd: 1(-3.9,4.4) 2(-3.9,3.75) 3(-3.9,3.1) 4(-3.9,2.45) 5(-3.9,1.8) 6(-3.9,1.15) 7(-3.9,0.5) 8(-3.9,-0.15) 9(-3.9,-0.8) 10(-3.9,-1.45) 11(-3.9,-2.1) 12(-3.9,-2.75) 13(-3.9,-3.4) 14(-3.9,-4.05) 15(3.9,-4.05) 16(3.9,-3.4) 17(3.9,-2.75) 18(3.9,-2.1) 19(3.9,-1.45) 20(3.9,-0.8) 21(3.9,-0.15) 22(3.9,0.5) 23(3.9,1.15) 24(3.9,1.8) 25(3.9,2.45) 26(3.9,3.1) 27(3.9,3.75) 28(3.9,4.4)
  silkscreen extent -3,4.38 -2.75,4.63
"GPS Gms-g6a" [mm] "20-Pin Small Outline Integrated Circuit 3 mm Pitch, IPC Low Density"
  rect 2x0.8 smd: 1(-8,6.85) 2(-8,5.35) 3(-8,3.85) 4(-8,2.35) 6(-8,-0.6) 9(-8,-5.15) 10(-8,-6.65) 11(7.95,-6.65) 12(7.95,6.85)
  rect 2x0.7 smd: 5(-8,0.85) 7(-8,-2.2) 8(-8,-3.6)
  silkscreen extent -6.25,-7.4 8.05,7.65
HC-49U [mm] "Quartz Crystal, Thru-Hole; 2 Leads; Body 11.35 x 4.65 x 13.46 mm (LxWxH max)"
  oct 1.4x1.4 hole 0.8: 1(-2.44,0)
  round 1.4 hole 0.8: 2(2.44,0)
  silkscreen extent -5.7,-2.35 5.7,2.35
HDR1X2 [mm] "Connector; Header; 2 Position"
  rect 1.5x1.5 hole 0.9: 1(0,0)
  round 1.5 hole 0.9: 2(2.54,0)
  silkscreen extent -1.27,-1.27 3.81,1.27
HDR2X3_CEN [mm] "Connector; Header; 3x2 Position"
  rect 1.5x1.5 hole 0.9: 1(0,0)
  round 1.5 hole 0.9: 2(2.54,0) 3(5.08,0) 4(0,2.54) 5(2.54,2.54) 6(5.08,2.54)
  silkscreen extent -1.27,-1.27 6.35,3.81
Key [mm]
  round 1.8 hole 1: 1(1.2,7.45) 2(5.7,7.45)
  round 2 hole 1.3: 3(0,9.95) 4(7,10)
"LCD 2.8" [mm] "20-Pin Small Outline Integrated Circuit 1.27 mm Pitch, IPC Low Density"
  oval 5x0.4 smd: 1(-11.2,4) 2(-11.2,3.2) 3(-11.2,2.4) 4(-11.2,1.6) 5(-11.2,0.8) 6(-11.2,0) 7(-11.2,-0.8) 8(-11.2,-1.6) 9(-11.2,-2.4) 10(-11.2,-3.2) 11(-11.2,-4) 12(-11.2,-4.8) 13(-11.2,-5.6) 14(-11.2,-6.4) 15(-11.2,-7.2) 16(-11.2,-8) 17(-11.2,-8.8) 18(-11.2,-9.6)
  silkscreen extent -26,-10.5 -14.85,5
lsm303dlhc [mm] "20-Pin Small Outline Integrated Circuit 1.27 mm Pitch, IPC Low Density"
  rect 1.5x0.5 smd: 1(-1.5,1.95) 2(-1.5,1.15) 3(-1.5,0.35) 4(-1.5,-0.45) 5(-1.5,-1.25) 6(-1.5,-2.05) 8(1.5,-2.05) 9(1.5,-1.25) 10(1.5,-0.45) 11(1.5,0.35) 12(1.5,1.15) 13(1.5,1.95)
  rect 0.5x1.5 smd: 7(0,-2.4) 14(0,2.4)
  silkscreen extent -1.1,-1.35 0.4,3.07
microSD_PCB [mm]
  round 1.6 hole 1.6: 0(2.5,-8.2)
  oval 1.6x1.5 hole 1.6: 0(2.5,1.8)
  rect 2x0.7 smd: 1(-1.1,-0.6) 2(-1.1,-1.7) 3(-1.1,-2.8) 4(-1.1,-3.9) 5(-1.1,-5) 6(-1.1,-6.1) 7(-1.1,-7.2) 8(-1.1,-8.3) 9(-1.1,0.5) 10(-1.1,1.6)
  rect 3x1.5 smd: GND(7.3,-10.75) GND(7.3,4.2)
  silkscreen extent 0,-10 12.15,3.5
PIN1 [mm] "Generic Antenna; 1 Lead"
  rect 1.5x1.5 hole 0.9: 1(0,0)
  silkscreen extent -1.4,-1.4 1.4,2.17
PIN2 [mm] "Photosensitive Diode; 2 Leads"
  rect 1.5x1.5 hole 0.9: 1(0,0)
  round 1.5 hole 0.9: 2(2.54,0)
  silkscreen extent -1.4,-1.4 3.94,2.18
R38 [mm] "Crystal, Thru-Hole; 2 Leads; Body 3.1 x 8.2 mm (Dia.xH)"
  round 1.3 hole 0.7: 1(0,1.55) 2(0,-1.55)
  silkscreen extent -1.55,-1.19 1.55,1.17
RGB_5mm_Led [mm] "20-Pin Small Outline Integrated Circuit 1.27 mm Pitch, IPC Low Density"
  oval 1.15x1.7 hole 0.6: 1(4.2,0) 2(2.8,0) 3(1.4,0)
  rect 1.15x1.7 hole 0.6: 4(0,0)
SIM900_ [mm] "20-Pin Small Outline Integrated Circuit 3 mm Pitch, IPC Low Density"
  oval 2x0.6 smd: 1(0,-4) 3(0,-5.95) 4(0,-7) 5(0,-8) 6(0,-9) 7(0,-10) 8(0,-11) 9(0,-11.95) 10(0,-13) 11(0,-14) 12(0,-15) 13(0.05,-16) 14(0.05,-17) 15(0.05,-17.95) 16(0.05,-19) 17(0.05,-20) 35(24.05,-20) 36(24.05,-19) 37(24.05,-17.95) 38(24.05,-17) 39(24.05,-16) 40(24,-15) 41(24,-14) 42(24,-13) 43(24,-11.95) 44(24,-11) 45(24,-10) 46(24,-9) 47(24,-8) 48(24,-7) 49(24,-5.95) 50(24,-5) 51(24,-4)
  oval 1.75x0.6 smd: 2(0,-5)
  oval 0.6x2 smd: 18(4,-24) 19(5,-24) 20(5.95,-24) 21(7,-24) 22(8,-24) 23(9,-24) 24(10,-24) 25(11,-24) 26(11.95,-24) 27(13,-24) 28(14,-24) 29(15,-24) 30(16,-23.95) 31(17,-23.95) 32(17.95,-23.95) 33(19,-23.95) 34(20,-23.95) 52(20,0.05) 53(19,0.05) 54(17.95,0.05) 55(17,0.05) 56(16,0.05) 57(15,0) 58(14,0) 59(13,0) 60(11.95,0) 61(11,0) 62(10,0) 63(9,0) 64(8,0) 65(7,0) 66(5.95,0) 67(5,0) 68(4,0)
  silkscreen extent 0.75,-22.35 22.5,-0.78
SIM-06 [mm] "20-Pin Small Outline Integrated Circuit 1.27 mm Pitch, IPC Low Density"
  rect 2x1 smd: 1(0.05,-12.5) 2(0.05,-10) 3(0,-7.5) 4(17.75,-7.5) 5(17.8,-10) 6(17.8,-12.5)
  silkscreen extent 0,-17.25 24.9,0
sma [mm] "20-Pin Small Outline Integrated Circuit 1.27 mm Pitch, IPC Low Density"
  round 2 hole 1.3: 1(0,0) 2(-2.5,-2.5) 3(2.55,-2.5) 4(2.5,2.5) 5(-2.5,2.5)
  silkscreen extent -2.5,-2.55 2.5,2.4
SMF05CT1G [mm]
  rect 1x0.4 smd: 1(-1.02,0.64) 2(-1.02,0) 3(-1.02,-0.65) 4(1.04,-0.68) 5(1.04,-0.03) 6(1.04,0.61)
  silkscreen extent -0.65,-1.08 0.31,1.59
SOIC8N_N [mm] "SOIC, 8-Leads, Body 4.9x3.9mm, Pitch 1.27mm, IPC Medium Density"
  oval 2.2x0.6 smd: 1(-2.4,1.905) 2(-2.4,0.635) 3(-2.4,-0.635) 4(-2.4,-1.905) 5(2.4,-1.905) 6(2.4,-0.635) 7(2.4,0.635) 8(2.4,1.905)
  silkscreen extent -2.52,-2.5 0.9,2.88, body extent -1.95,-2.45 1.95,2.45, height 1.75
SOT23_N [mm] "SOT23, 3-Leads, Body 2.9x1.3mm, Pitch 0.95mm, Lead Span 2.3mm, IPC Medium Density"
  rect 1.3x0.6 smd: 1(-1.05,0.95) 2(-1.05,-0.95) 3(1.05,0)
  silkscreen extent -1.18,-1.5 0.7,1.92, body extent -0.7,-1.5 0.7,1.5, height 1.1
SOT-23 [mm] "SOT-23; 3 Leads; Body 3.0 x 2.6 mm, inc. leads (LxW max)"
  rect 0.9x0.95 smd: 1(-0.95,-1.25) 2(0.95,-1.25) 3(0,1.25)
  silkscreen extent -2.07,-1.38 1.3,1.25
St_3V0 [mm] "20-Pin Small Outline Integrated Circuit 1.27 mm Pitch, IPC Low Density"
  rect 1.2x0.5 smd: 1(-1.1,0.7)
  oval 1.2x0.5 smd: 2(-1.1,-0.5) 3(1.1,-0.5) 4(1.1,0.7)
  silkscreen extent -0.5,-0.6 0.3,1.22
St_3V0_ver2 [mm] "20-Pin Small Outline Integrated Circuit 1.27 mm Pitch, IPC Low Density"
  rect 1.2x0.5 smd: 1(-1.35,1)
  oval 1.2x0.5 smd: 2(-1.35,-0.3) 3(0.85,-0.3) 4(0.85,1)
  silkscreen extent -0.75,-0.4 0.05,1.43
TC [mm] "20-Pin Small Outline Integrated Circuit 3 mm Pitch, IPC Low Density"
  rect 0.35x1.8 smd: 1(-2.173,-2.575) 2(-1.538,-2.575) 3(-0.903,-2.575) 4(-0.268,-2.575) 5(0.367,-2.575) 6(1.002,-2.575) 7(1.637,-2.575) 8(2.272,-2.575) 9(2.272,2.625) 10(1.637,2.625) 11(1.002,2.625) 12(0.367,2.625) 13(-0.268,2.625) 14(-0.903,2.625) 15(-1.538,2.625) 16(-2.173,2.625)
  silkscreen extent -3.05,-2.7 2.55,1.22
VT [mm] "20-Pin Small Outline Integrated Circuit 3 mm Pitch, IPC Low Density"
  rect 0.6x0.85 smd: 1(-0.95,-1.05) 2(0.95,-1.05) 3(0,1.1)
  silkscreen extent -1.5,-0.27 1.5,1.5, body extent -1.5,-0.67 1.5,0.73, height 1.1
Xmain [mm] "20-Pin Small Outline Integrated Circuit 1.27 mm Pitch, IPC Low Density"
  rect 3.6x1.5 smd: 1(6.8,-3.75) 2(6.8,-1.25) 3(6.8,1.3) 4(6.8,3.8)
  rect 3.6x1.5 smd far side: 5(6.8,-3.75) 6(6.8,-1.25) 7(6.8,1.3) 8(6.8,3.8)
  silkscreen extent -4.6,-5.85 6.65,5.8
ZQ [mm] "SOT-457/SC-74; 6 Leads; Body 3.1 x 2.9 mm, inc. leads (LxW max)"
  rect 4.5x2 smd: 1(-7.62,0) 2(0.635,0)
  silkscreen extent -10.03,-2.29 3.05,2.29
Датчик [mm] "20-Pin Small Outline Integrated Circuit 1.27 mm Pitch, IPC Low Density"
  rect 1x0.4 smd: 1(-1.55,1) 2(-1.55,0) 3(-1.55,-1) 4(1.65,-1) 5(1.65,0) 6(1.65,1)
  silkscreen extent -0.75,-1.35 0.8,1.35
"Датчик давления Bmp085" [mm] "20-Pin Small Outline Integrated Circuit 1.27 mm Pitch, IPC Low Density"
  rect 2x0.8 smd: 1(-3.05,1.8) 2(-3.05,0.5) 3(-3.05,-0.8) 5(1.95,-0.8) 6(1.95,0.5) 7(1.95,1.8)
  rect 0.8x2 smd: 4(-0.5,-2)
  rect 0.8x2.5 smd: 8(-0.55,2.65)
  silkscreen extent -2.65,-1.35 0.55,2.77
"Преобразователь уровней SN74LVC1T45" [mm] "20-Pin Small Outline Integrated Circuit 0.95 mm Pitch"
  rect 1.5x0.5 smd: 1(-3,1.9) 2(-3,0.95) 3(-3,0) 4(0,0) 5(0,0.95) 6(0,1.9)
  silkscreen extent -2.65,-0.55 -1.1,2.77

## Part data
BT1: "Multicell Battery"
C1 C3 C4 C5 C6 C7 C8 C9 C10 C11 C12 C13 C14 C15 C16 C17 C18 C19 C20 C21 C22 C23 C24 C25 C26 C27 C28 C29 C30 C31 C34 C35 C36 C37 C39 C40 C41 C42 C43 C44 C45 C46 C47 C48 C49 C50 C51 C53 C54 C55 C56 C57 C58 C59 C60 C61 C62 C64 C65 C66 C67 C68 C69 C70 C71 C72 C73 C74 C75 C76: "Capacitor (Semiconductor SIM Model)"
C2 C32 C33 C38 C52 C63: "Polarized Capacitor (Axial)"
D1 D5: "Silicon AF Schottky Diode for High-Speed Switching"
D2 D3: "Typical BLUE SiC LED"
D4: library part "D Tunnel1", "Tunnel Diode - RLC Model"
E1: "Generic Antenna"
J1: "USB On-The-Go (OTG) Mini-B Receptacle, Right Angle, SMT, 0.80mm (.031\") Pitch, Solder Tabs with Back Cover, Recessed Type"
J2 J3: "3-Conductor Jack with 2 break contacts (normals) and 2 auxiliary make contacts"
LS1: "Magnetic Transducer Buzzer"
LS2: "Loudspeaker"
MK1 MK2: "Microphone"
P1: "Header, 3-Pin, Dual row"
P2: "RF Coaxial PCB Connector, MMCX; Thru-Hole, Vertical Mount Plug,  50 Ohm Impedance"
Q1: library part BC817-25, "NPN General-purpose Transistor"
Q2 Q3 Q4 Q5 Q6 Q7: library part MOSFET-P, "P-Channel MOSFET"
Q8: library part BC847, "NPN General-purpose Transistor"
R1 R2 R3 R4 R5 R6 R7 R8 R9 R10 R11 R12 R13 R14 R15 R16 R17 R18 R19 R20 R21 R22 R23 R24 R25 R26 R27 R28 R29 R30 R31 R32 R33 R34 R35 R36 R37 R38 R39 R40 R41 R42 R43 R44 R45 R46 R47 R48 R49 R50 R51 R52 R53 R54 R55 R56 R57 R58 R59 R60: "Resistor"
S1 S2 S3: library part Key_u
U2: "2.8\"LCD SPI (ILI9341)"
U3: "8 MHz 8-bit AVR Microcontroller with 256KB Flash, 100-Pin TQFP Pkg, 86 I/Os, 12 PWMs, 4 USARTs, 16 ADC Channels, Industrial Temp"
U4: library part SN74LVC1T45, "Преобразователь уровней"
U5: library part ADS7846E/2K5, "4-Wire Touch Screen Controller, 16-Pin SSOP"
U6: "SIM card"
U13 U22: library part MCP1700T-1202E/TT, "Low Quiescent Current LDO, 3-Pin SOT-23, Extended Temperature, Tape and Reel"
U15: library part TEA5767
U17 U20 U21: library part ncp698sq30T1
U18: library part "KXO-V97 генератор", "Generator"
U23: library part micro_SD
U25: "I2C Serial Real-Time Clock (RTC), 3.0V, 8-Pin uMax/uSOP"
VD1: library part RGB_Led
Y1 Y3: library part XTAL, "Crystal Oscillator"
Y2: library part ECS-240-20-1, "Crystal Oscillator"
Y4: "Crystal Oscillator"

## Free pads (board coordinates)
  round 4.5 hole 3: 0(169.05,103.075) 0(169.05,149.025)

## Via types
v1: diameter 0.8, hole 0.3, Top Layer to Bottom Layer, 158 vias
v2: diameter 0.8, hole 0.3, Top Layer to Mid-Layer 1, 69 vias
v3: diameter 0.8, hole 0.3, Mid-Layer 2 to Bottom Layer, 18 vias
v4: diameter 0.7, hole 0.3, Top Layer to Bottom Layer, 9 vias
v5: diameter 0.7, hole 0.3, Top Layer to Mid-Layer 1, 5 vias
v6: diameter 0.8, hole 0.3, Top Layer to Mid-Layer 1, tented top, 1 vias
v7: diameter 0.8, hole 0.3, Top Layer to Bottom Layer, tented top, 1 vias
v8: diameter 1, hole 0.5, Top Layer to Bottom Layer, 1 vias

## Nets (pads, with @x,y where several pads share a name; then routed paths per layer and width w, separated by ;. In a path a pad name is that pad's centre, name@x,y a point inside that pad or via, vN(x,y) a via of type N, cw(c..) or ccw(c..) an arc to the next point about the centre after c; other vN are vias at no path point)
A_CPU_ON: R33.2 U3.75 | length 25.9
  Top Layer w0.25: v1(202.475,117.55) 205.322,117.55 U3.75@205.586,117.286
  Bottom Layer w0.25: R33.2@182.15,123.5 182.418,123.5 185.618,120.3 192.883,120.3 195.358,117.825 201.95,117.825 v1@202.325,117.45
ADC_AUDIO: C58.2 R51.1 U3.97 | length 10.6
  Top Layer w0.25: U3.97@204.036,105.236 205.829,105.236 206.3,105.236 207.75,106.686 v1@207.75,106.75
  Bottom Layer w0.25: v1(207.875,106.85) 208.25,106.475 R51.1@208.25,102.75 C58.2@210.25,102.75
AGND: C32.2 C33.2 C35.2 C36.2 C37.2 C42.1 C46.1 C52.2 C53.2 C54.2 C69.1 C70.2 C74.2 C75.1 J2.1 J3.1 R39.1 R41.2 R42.2 U16.28 U24.37 U24.40 U24.41 U24.47 | length 136.9
  Top Layer w0.25: J3.1@161.5,113.8 J3.1@162.1,114.4 ; v4(175.6,110.85) 175.7,110.75 U16.28@177.45,110.75 ; C52.2@175.75,118.1 175.85,118.2 v2@176.55,118.2 ; v2@176.826,117.924 177.75,117 177.925,117.175 C53.2@178,117.175 ; C54.2@182.75,117.25 v2(183.775,117.25) C74.2@184.75,117.25 ; U24.47@195.15,110.025 195.15,110.925 195.4,111.175 195.455,111.175 196.25,111.97 C75.1@196.25,112.25 196.25,112.675 196.975,113.4 198.4,113.4 199.25,112.55 C70.2@199.25,112.25 199.25,111.235 199.375,111.185 ; U24.41@198.15,110.025 198.15,111.075 198.54,111.075 198.65,111.185 ; U24.40@198.65,110.025 198.65,111.185 ; 200.04,111.185 199.375,111.185 ; U24.37@200.15,110.025 200.15,111.125 v1@200.4,111.375 ; 198.65,111.185 199.375,111.185
  Top Layer w0.3: C37.2@172.5,101.25 C42.1@174.75,101.25 175.6,101.25 176.125,100.725 180.625,100.725 181.15,101.25 C46.1@182,101.25 v1(183.125,101.25) R39.1@184.25,101.25
  Top Layer w0.5: v1(168.225,113.6) R42.2@169.5,113.6
  Top Layer w0.7: J3.1@162.1,114.4 165.325,114.4 166.125,113.6 R41.2@167,113.6 v1(168.225,113.6)
  Top Layer w1: J3.1@161.5,113.8 J2.1@161.5,125.8
  Mid-Layer 1 w0.25: v2@176.85,117.85 178.125,116.575 183.1,116.575 v2(183.775,117.25)
  Mid-Layer 1 w0.55: v4(175.6,110.85) 175.625,110.825 175.625,110.175
  Mid-Layer 1 w0.7: 175.625,110.175 175.05,109.6 173.25,109.6 169.25,113.6 v1(168.225,113.6) 170.075,115.45 172.9,115.45 175.4,117.95 v2@176.809,117.95 ; 193.45,113.55 193.45,112.125 194.1,111.475 v1(200.375,111.475)
  Mid-Layer 1 w1: J2.1@161.55,126.025 161.55,131.075 168.275,137.8 170.275,137.8
  Bottom Layer w0.25: C32.2@175,116.15 175.112,116.037 C32.2@175.5,115.65 ; 175.5,111.8 175.6,111.7 ; 179.5,109.275 C35.2@179.5,107.75 179.5,104.875 v1(183.125,101.25) ; v1@200.375,111.25 v1(200.375,111.475)
  Bottom Layer w0.4: v4(175.6,110.85) 175.6,111.7
  Bottom Layer w0.5: C69.1@198.5,109.375 198.563,109.437 v1@200.375,111.25
  Bottom Layer w0.7: J3.1@161.5,113.8 163.35,115.65 175.075,115.65 C32.2@175.15,115.65 ; C32.2@175,116.15 C36.2@175,118.25
  other v2: 176.809,117.906
AUX_OUT_L: C8.2 C58.1 C71.2 U1.19 U16.21 | length 93.8
  Top Layer w0.25: U16.21@179.75,113.05 179.75,114.9 179.75,115.5 C71.2@180,115.75 ; U1.19@210,131.25 211.75,131.25 C8.2@212,131 212,129.825 212.15,129.675 213.55,129.675 v1@213.575,129.675
  Mid-Layer 2 w0.25: v3@211.7,101.125 211.65,101.075 211.35,100.775 190.35,100.775 179.825,111.3 v1(179.825,114.9) 179.825,123.025 183.825,127.025 206.328,127.025 208.953,129.65 213.55,129.65 v1@213.575,129.65
  Bottom Layer w0.25: C58.1@210.25,101.25 210.375,101.125 211.575,101.125 v3@211.7,101.125
  other v1: 213.55,129.475
  other v3: 211.575,101.15
AUX_OUT_R: C76.2 U16.22 | length 17.3
  Top Layer w0.25: v5@178.775,114.5 179.25,114.025 U16.22@179.25,113.05 ; v2@184.3,109.025 v2@184.309,109.016 ; v2(184.309,108.955) v2@184.309,109.016 ; C76.2@191,110.5 191,110.025 190.075,109.1 186.325,109.1 185.9,108.675 184.65,108.675 184.339,108.986 v2@184.309,109.016
  Mid-Layer 1 w0.25: v5@178.875,114.5 v2@184.325,109.05
  other v5: 178.85,114.6
BSYNC: U3.4 U24.13 | length 16.4
  Top Layer w0.25: v2(193.65,101.525) 194.1,101.975 U24.13@194.65,101.975 ; v6(207,100.65) 207.086,100.736 U3.4@207.086,102.186
  Mid-Layer 1 w0.25: v2@193.8,101.675 194.225,101.25 206.4,101.25 v6(207,100.65)
CART_DETECT: U3.25 U23.10 | length 47.3
  Top Layer w0.25: U3.25@217.586,102.186 v2@219.111,102.186
  Mid-Layer 1 w0.25: v2(219.275,102.35) 219.275,104.811 219.85,105.386 219.85,108.565 220.175,108.89 220.175,108.921 222.254,111 223.525,111 228,115.475 228,118.375 230.275,120.65 230.275,131.275 230.425,131.425 230.412,131.437 v1@230.275,131.575
  Bottom Layer w0.25: U23.10@220.4,131.65 221.85,131.65 223.025,132.825 224.725,132.825 225.975,131.575 v1(230.55,131.575)
CD_CART_POW: C66.2 C67.1 R54.1 R55.1 U20.3 U23.4 | length 13
  Bottom Layer w0.4: R55.1@213.25,136.75 214.75,135.25 C67.1@215.25,135.25 215.85,134.65 C66.2@217.5,134.65 ; U20.3@216.95,131.35 216.95,132.75 216.95,132.8 216.875,132.875 216.75,133 216.75,133.9 217.375,134.525 C66.2@217.5,134.65 ; U23.4@220.4,137.15 219.514,137.15 218.95,136.586 218.95,136.1 C66.2@217.5,134.65
CLOCK_BATT: D1.3 U1.26 | length 2.2
  Top Layer w0.25: U1.26@210,138.2 211.45,138.2 D1.3@212,138.75
CS_TC: U3.74 U5.15 | length 41.6
  Top Layer w0.25: v1@172.5,124.85 172.662,125.012 U5.15@172.662,126.6 ; v1(196.825,120) 197.275,119.55 201.525,119.55 202.37,118.705 205.77,118.705 206.086,118.389 U3.74@206.086,117.286
  Mid-Layer 1 w0.3: v1(172.375,124.7) 173.125,125.45 182.125,125.45 189.8,117.775 192.675,117.775 194.825,119.925 v1@196.7,119.925
CS_VS: R53.2 U3.1 U24.23 | length 9.7
  Top Layer w0.25: U24.23@199.65,101.975 199.65,100.925 200.4,100.175 204.675,100.175 205.586,101.086 U3.1@205.586,102.186 ; 202.25,100.3 R53.2@202.25,101.25
D/I: U2.4 U3.68 | length 36.8
  Top Layer w0.25: U2.4@180.8,130.6 v2@184,130.6 ; U3.68@209.086,117.286 209.086,115.839 v2(209.4,115.525)
  Mid-Layer 1 w0.25: v2@184.025,130.6 194.675,130.6 209.312,115.963 v2@209.312,115.612
  other v2: 184.025,130.45
DISP_RST_X: U2.2 U3.66 | length 41
  Top Layer w0.25: U2.2@180.8,132.2 v2@183.975,132.2 ; U3.66@210.086,117.286 210.086,116.139 210.825,115.4 v2(211.225,115.4) v2@211.325,115.4
  Mid-Layer 1 w0.25: v2@184.025,132.2 184.175,132.05 v2(184.25,132.05) 185.2,133 194.15,133 211.185,115.965 211.185,115.525 v2@211.2,115.525
DREG_MP3: U3.6 U24.8 | length 21.6
  Top Layer w0.25: v2@191.75,105.425 191.925,105.25 U24.8@193.375,105.25 ; U3.6@208.086,102.186 208.086,103.686 v2(208.125,103.725)
  Mid-Layer 1 w0.25: v2(191.65,105.375) 193.46,105.375 196.185,102.65 202.25,102.65 203.205,103.605 208.037,103.605 208.037,103.725 208.037,103.887 v2@208.125,103.975
E(CS_LCD): U2.5 U3.69 | length 46.4
  Top Layer w0.25: v2@177.525,129.75 177.575,129.8 U2.5@180.8,129.8 ; U3.69@208.586,117.286 208.586,115.114 209.175,114.525 v2@209.75,114.525
  Mid-Layer 1 w0.25: v2@177.375,129.675 177.4,129.675 177.425,129.7 177.45,129.675 184.346,129.675 184.771,130.1 194.468,130.1 208.45,116.118 208.45,115.379 209.348,114.481 v2(209.76,114.481)
  other v2: 177.4,129.725
E_POW_CART: U3.56 U20.4 | length 18.9
  Top Layer w0.25: v1(215.05,118.825) 215.086,118.789 U3.56@215.086,117.286
  Mid-Layer 2 w0.25: v1(215.05,118.825) 215.975,118.825 220.695,123.545 220.695,126.259 219.65,127.304 219.65,130.2 v3(220.025,130.575)
  Bottom Layer w0.25: U20.4@218.25,131.35 218.375,131.225 219.025,130.575 v3(220.025,130.575)
FM_ANT: E1.1 U15.10 | length 3.5
  Top Layer w0.4: E1.1@186.25,113.25 E1.1@186.5,113.25 ; U15.10@188.75,114.45 U15.10@189.3,114.45
  Top Layer w0.6: E1.1@186.5,113.25 186.75,113.25 187.55,113.25 U15.10@188.75,114.45
FON: R48.1 U3.40 | length 38.9
  Top Layer w0.25: v2@216.621,109.8 217.557,110.736 ; 217.586,110.736 U3.40@219.136,110.736 ; v2@221.25,141.25 R48.1@221.25,143.45
  Mid-Layer 1 w0.25: v2(216.261,109.83) 216.462,109.83 218.835,112.203 218.835,116.632 221.8,119.597 221.8,140.7 v2(221.425,141.075)
G_24.576: U16.11 U18.3 | length 2.9
  Top Layer w0.25: U16.11@182.55,109.75 184.825,109.75 185.195,110.12 U18.3@185.095,110.12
